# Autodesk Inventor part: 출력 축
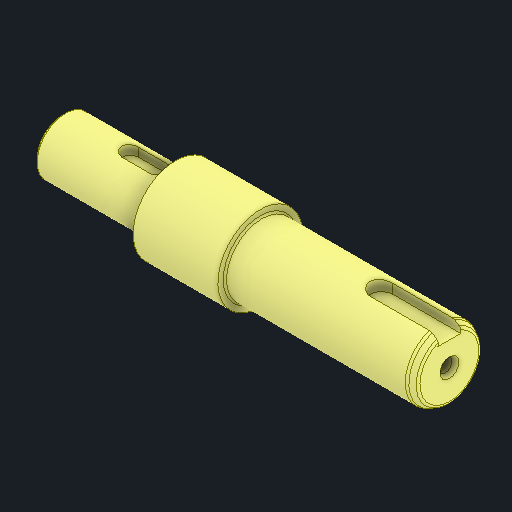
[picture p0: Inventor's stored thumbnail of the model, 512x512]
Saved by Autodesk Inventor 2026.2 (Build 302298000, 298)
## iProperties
Created: 2025-11
Part Number: 출력 축
Material: 강철, 탄소
Document SubType Name: Modeling
Designer: PC2-07
Density: 7.85 g/cm^3
Appearance: 기본값
Author: jhkim
Sending System: Autodesk Inventor 2026
Preprocessor: ST-DEVELOPER v20.1
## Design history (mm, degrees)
feature "솔리드1"
node "솔리드2"
